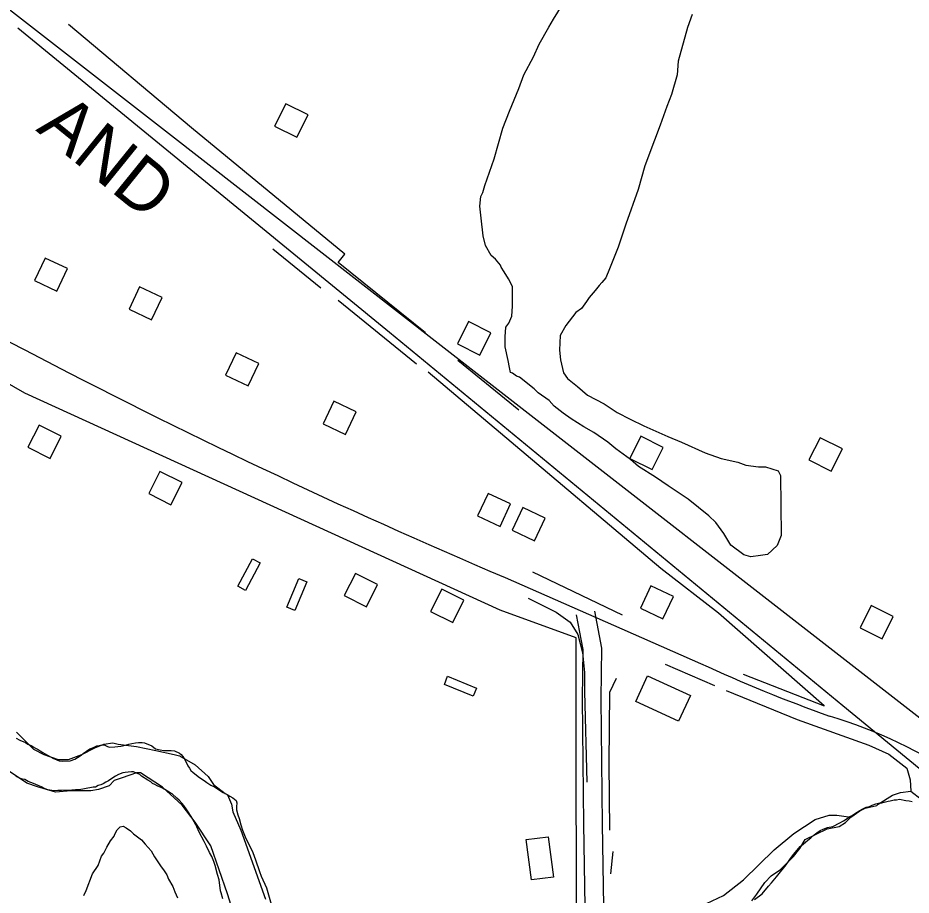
# Model space of a CAD drawing. Extents: x 3250478 to 3288318, y 788638 to 816472.
# Drawn here: x 3257033 to 3258470, y 796061 to 797471 of the extents above; entities that cross this region are included whole.
import ezdxf

# ---------------------------------------------------------------- set-up
doc = ezdxf.new("R2010")
doc.units = 0
for name, color, linetype in [('V-BLDG-OTLN', 7, 'Continuous'), ('V-RAIL-IDEN', 7, 'Continuous'), ('V-RAIL-TRAK', 7, 'Continuous'), ('V-ROAD-CNTR', 7, 'Continuous'), ('V-SITE-VEGE', 7, 'Continuous'), ('V-TOPO-SHOR', 7, 'Continuous')]:
    doc.layers.add(name, color=color, linetype=linetype)

msp = doc.modelspace()

# ---------------------------------------------------------------- linework, layer by layer
at = {"layer": 'V-BLDG-OTLN'}
for points in [[(3257446, 797297.2), (3257481.8, 797279.3), (3257499.7, 797315.1), (3257463.9, 797333)], [(3257059.7, 797048.9), (3257095.9, 797031.8), (3257112.9, 797067.9), (3257076.8, 797085)], [(3257211.8, 797002.7), (3257247.9, 796985.6), (3257265, 797021.7), (3257228.8, 797038.8)], [(3257740.1, 796946.9), (3257775.9, 796929), (3257793.8, 796964.8), (3257758, 796982.7)], [(3257367.1, 796896.6), (3257403.2, 796879.5), (3257420.3, 796915.7), (3257384.2, 796932.8)], [(3257523.9, 796818.5), (3257560, 796801.5), (3257577.1, 796837.6), (3257541, 796854.7)], [(3257102.8, 796798.6), (3257067.1, 796816.5), (3257049.1, 796780.7), (3257084.9, 796762.8)], [(3258017.3, 796762.8), (3258053, 796744.9), (3258070.9, 796780.6), (3258035.2, 796798.5)], [(3258305.4, 796760.5), (3258341.2, 796742.6), (3258359.1, 796778.3), (3258323.3, 796796.2)], [(3257297.1, 796724.1), (3257261.3, 796742), (3257243.4, 796706.3), (3257279.1, 796688.4)], [(3257772.4, 796670.5), (3257808.5, 796653.4), (3257825.6, 796689.6), (3257789.5, 796706.7)], [(3257828, 796647.6), (3257864.2, 796630.5), (3257881.3, 796666.7), (3257845.1, 796683.8)], [(3257422.7, 796594.9), (3257399.2, 796550.7), (3257386.9, 796557.3), (3257410.4, 796601.5)], [(3257497.7, 796564.6), (3257478.6, 796518.4), (3257465.7, 796523.7), (3257484.8, 796569.9)], [(3257611.6, 796560.2), (3257575.8, 796578.1), (3257557.9, 796542.4), (3257593.7, 796524.4)], [(3257750.4, 796534.8), (3257714.7, 796552.8), (3257696.7, 796517), (3257732.5, 796499.1)], [(3258034.2, 796521.9), (3258070.4, 796504.8), (3258087.4, 796541), (3258051.3, 796558.1)], [(3258387.5, 796490.8), (3258423.2, 796472.9), (3258441.1, 796508.6), (3258405.4, 796526.5)], [(3257724.2, 796412.6), (3257770.6, 796393.8), (3257765.3, 796380.8), (3257719, 796399.6)], [(3258095.6, 796340.4), (3258026.7, 796371.9), (3258045.7, 796413.4), (3258114.6, 796381.9)], [(3257859.2, 796085.4), (3257850.8, 796150.2), (3257886, 796154.8), (3257894.5, 796090)]]:
    msp.add_lwpolyline(points, close=True, dxfattribs=at)
at = {"layer": 'V-RAIL-TRAK'}
for p, q in [((3256836.1, 797626.6), (3257270.3, 797289.2)), ((3257270.3, 797289.2), (3257708.9, 796948.1)), ((3257708.9, 796948.1), (3258784.7, 796111.9))]:
    msp.add_line(p, q, dxfattribs=at)
at = {"layer": 'V-ROAD-CNTR'}
for points in [[(3257460.7, 794021.9), (3257497.3, 794112.9), (3257860.4, 794882.3), (3257924.8, 795086.6), (3257932, 795269.1), (3257930.7, 796474.2), (3257808.6, 796519), (3257044, 796867.7), (3256342, 797271.9), (3255916.7, 797438.8), (3254738.6, 797696.6), (3254639.1, 797722.8)], [(3257033, 797455), (3257630.9, 796965.7), (3258360.1, 796365.5), (3258907.8, 795916), (3259260.7, 795624.6)], [(3256332.7, 797305.7), (3256597.4, 797165.1), (3257044.1, 796937.5)], [(3257816.7, 796571.3), (3257991, 796494.9), (3258130.7, 796433.4)], [(3257960.8, 795434.7), (3257959.7, 795538.8), (3257948.6, 795843.8), (3257943.1, 796174.8), (3257941.3, 796376.3), (3257942.4, 796455.5), (3257931.6, 796511.6)], [(3257981.1, 795776.3), (3257978.6, 795844.6), (3257973.1, 796175.2), (3257971.3, 796376.3), (3257972.5, 796458.1), (3257961.1, 796517.3)]]:
    msp.add_lwpolyline(points, dxfattribs=at)
for centre, radius, start, end in [((3261963.5, 806320), 10594, 242.33113, 246.95669), ((3259154.7, 798645.7), 2437.7, 245.163, 250.4344), ((3258105.2, 795581.8), 801.6, 56.0289, 73.0938)]:
    msp.add_arc(centre, radius, start, end, dxfattribs=at)
at = {"layer": 'V-SITE-VEGE'}
for points in [[(3257943.4, 796813.9), (3257922.7, 796826.4), (3257909.9, 796835.7), (3257895.5, 796846.6), (3257887.5, 796856), (3257869.9, 796868.5), (3257863.5, 796874.8), (3257839.6, 796893.5), (3257834.8, 796895), (3257828.4, 796899.7), (3257825.2, 796901.2), (3257823.5, 796909.1), (3257821.8, 796920.2), (3257816.8, 796942.3), (3257816.6, 796958.1), (3257818, 796974), (3257822.7, 796980.4), (3257827.3, 796991.5), (3257828.7, 797007.4), (3257828.4, 797039), (3257821.9, 797051.6), (3257815.4, 797062.6), (3257810.6, 797070.5), (3257809, 797073.6), (3257801, 797083), (3257794.5, 797089.3), (3257784.9, 797105), (3257781.5, 797120.8), (3257778, 797149.3), (3257776.2, 797168.2), (3257777.6, 797184.1), (3257780.7, 797190.5), (3257783.8, 797201.6), (3257799.1, 797244.5), (3257812.8, 797293.8), (3257823.5, 797320.8), (3257839, 797357.4), (3257846.6, 797379.6), (3257862.1, 797408.3), (3257871.4, 797429), (3257886.9, 797456.1), (3257894.7, 797468.9), (3257908.7, 797491.2)], [(3258117.8, 797476.2), (3258110.2, 797455.5), (3258094.9, 797401.5), (3258093.6, 797379.3), (3258084.5, 797347.6), (3258076.8, 797328.5), (3258066.1, 797298.3), (3258056.8, 797274.4), (3258041.5, 797233.1), (3258030.8, 797194.9), (3258010.9, 797139.3), (3257998.6, 797102.7), (3257984.8, 797067.7), (3257978.6, 797053.4), (3257972.4, 797045.4), (3257967.7, 797040.6), (3257961.5, 797032.6), (3257952.1, 797021.4), (3257947.4, 797015.1), (3257939.6, 797003.9), (3257930.2, 796997.4), (3257914.6, 796976.7), (3257905.3, 796960.7), (3257904, 796937), (3257905.7, 796921.2), (3257910.7, 796900.6), (3257917.2, 796891.2), (3257933.1, 796878.7), (3257949.1, 796864.7), (3257976.2, 796850.7), (3257997, 796836.7), (3258017.7, 796825.9), (3258040, 796815), (3258078.2, 796798.1), (3258100.4, 796788.8), (3258138.6, 796771.8), (3258164.1, 796762.6), (3258191.1, 796756.6), (3258203.8, 796752), (3258224.4, 796749.1), (3258235.5, 796749.2), (3258256.1, 796743.1), (3258259.4, 796735.2), (3258260.5, 796638.7), (3258254.4, 796622.8), (3258238.7, 796608.3), (3258227.6, 796606.6), (3258211.8, 796604.9), (3258200.7, 796607.9), (3258179.9, 796623.5), (3258168.6, 796642.4), (3258155.8, 796659.6), (3258144.6, 796670.6), (3258111, 796697.1), (3258079.1, 796718.9), (3258058.3, 796732.9), (3258031.2, 796750), (3258018.4, 796761), (3257994.5, 796778.1), (3257981.7, 796789), (3257959.3, 796804.6), (3257943.4, 796813.9)], [(3257030.1, 796313.2), (3257036.1, 796310), (3257045.3, 796306), (3257049, 796303.8), (3257055.3, 796301), (3257059.4, 796298.4), (3257065.4, 796295.2), (3257069.1, 796292.6), (3257073.2, 796290.1), (3257080.6, 796286.1), (3257090.3, 796280.7), (3257095.8, 796278.2), (3257099.5, 796276.7), (3257105.4, 796276.4), (3257116.9, 796276.6), (3257124.6, 796279.6), (3257133.4, 796284.9), (3257139.9, 796290.1), (3257143.6, 796292.4), (3257148.7, 796295.8), (3257154.6, 796298.4), (3257160.1, 796301.1), (3257163.8, 796301.5), (3257168.2, 796302.3), (3257171.9, 796302.3), (3257176, 796300.1), (3257179.7, 796298.7), (3257188.9, 796299.2), (3257193.7, 796300), (3257198.8, 796300.4), (3257206.2, 796302), (3257211.4, 796303.5), (3257216.1, 796304.7), (3257222.4, 796305.8), (3257226.8, 796306.3), (3257233.1, 796306.3), (3257236.8, 796305.6), (3257248.3, 796300.6), (3257254.6, 796296.2), (3257261.6, 796294.5), (3257267.9, 796293.4), (3257279.4, 796293.6), (3257284.9, 796292.9), (3257293, 796289.3), (3257295.7, 796286.8), (3257300.1, 796281.6), (3257302.4, 796276.5), (3257306.6, 796268.8), (3257309.2, 796265.2), (3257311.4, 796261.1), (3257314.8, 796257.8), (3257325.2, 796249.8), (3257332.7, 796245.1), (3257336.8, 796241.9), (3257343.4, 796237.9), (3257349, 796235), (3257357.2, 796229.6), (3257363.1, 796225.9), (3257370.6, 796222), (3257373.9, 796219.8), (3257378.7, 796217.3), (3257383.9, 796212.9), (3257385.1, 796209.2), (3257384.8, 796202.9), (3257384.8, 796198.1), (3257386.8, 796189.7), (3257389.1, 796184.2), (3257391.8, 796173.9), (3257394.4, 796165.4), (3257399.8, 796151.8), (3257404.3, 796143), (3257410.7, 796129.5), (3257415.3, 796117.7), (3257421.8, 796098.6), (3257424.4, 796091.6), (3257433.1, 796072.5), (3257441.2, 796042.4)], [(3257157.6, 796234.6), (3257154.2, 796234.2), (3257139.9, 796231.5), (3257131.4, 796230.3), (3257125.5, 796230.2), (3257120, 796229.4), (3257103.4, 796229.2), (3257097.1, 796228.8), (3257090.9, 796228.7), (3257081.2, 796230.1), (3257075.7, 796232.2), (3257070.9, 796234.7), (3257065.7, 796236.9), (3257058.3, 796240.5), (3257049.7, 796243.7), (3257044.2, 796246.6), (3257040.5, 796247.3), (3257037.1, 796248.4), (3257030.5, 796251.6)], [(3257362.5, 796054.8), (3257359.8, 796064.7), (3257358.7, 796068), (3257356.6, 796085.7), (3257354.3, 796093.8), (3257350.5, 796108.5), (3257348.2, 796114.7), (3257344.8, 796123.2), (3257341.4, 796129.4), (3257336.5, 796139.7), (3257332.7, 796147), (3257324.8, 796162), (3257320.6, 796170.8), (3257319.1, 796173.8), (3257314.2, 796182.2), (3257311.6, 796187.3), (3257306.7, 796194.7), (3257303.7, 796199.4), (3257299.9, 796204.9), (3257296.6, 796208.6), (3257292.4, 796213.7), (3257288.7, 796217), (3257280.9, 796223.5), (3257276.1, 796226.4), (3257273.5, 796228.2), (3257270.5, 796230), (3257262.3, 796234.4), (3257258.2, 796236.2), (3257253.1, 796238.7), (3257249.7, 796240.5), (3257246.7, 796243), (3257241.9, 796245.6), (3257231.9, 796252.1), (3257228.9, 796254.6), (3257223.7, 796256.8), (3257219.2, 796258.9), (3257215.6, 796259.3), (3257210.4, 796258.8), (3257205.6, 796258.1), (3257201.6, 796257.6), (3257194.6, 796255), (3257190.2, 796252.3), (3257184, 796248.2), (3257178.8, 796244.5), (3257174.4, 796242.2), (3257170.4, 796239.9), (3257166.4, 796238), (3257162, 796236.9), (3257157.6, 796234.6)], [(3258268.6, 796109.5), (3258272.3, 796114.7), (3258275.9, 796119.5), (3258281, 796126.6), (3258291.2, 796138.9), (3258296.3, 796143), (3258303.6, 796149.4), (3258308.4, 796153.1), (3258313.8, 796158), (3258318.2, 796161), (3258323.3, 796164.7), (3258328.1, 796167), (3258335.1, 796169.7), (3258343.9, 796171.2), (3258354.9, 796177.3), (3258361.2, 796180.3), (3258365.2, 796182.9), (3258371, 796187.4), (3258375.1, 796188.9), (3258378.4, 796191.5), (3258387.2, 796196.8), (3258391.9, 796199.5), (3258397.4, 796202.1), (3258402.6, 796203.6), (3258407.3, 796205.5), (3258412.9, 796207.4), (3258417.3, 796208.6), (3258422.8, 796209.4), (3258426.5, 796210.2), (3258432.7, 796212.1), (3258436, 796212.5), (3258442.3, 796214.1), (3258446.4, 796214.1), (3258451.1, 796214.9), (3258461.1, 796213.2), (3258466.7, 796212.5), (3258471.5, 796211.4)], [(3257139, 796060.5), (3257142.8, 796068.4), (3257153.2, 796094.9), (3257161.9, 796108.7), (3257167.6, 796123.4), (3257171.4, 796128.3), (3257176.2, 796138.1), (3257181.9, 796148), (3257187.7, 796155.9), (3257188.7, 796158.8), (3257192.5, 796165.7), (3257197.3, 796170.6), (3257202.2, 796171.7), (3257207.1, 796168.8), (3257214, 796164), (3257219, 796159.2), (3257231.8, 796149.5), (3257237.7, 796142.8), (3257247.6, 796132.1), (3257252.6, 796122.4), (3257262.6, 796107.9), (3257268.5, 796100.1), (3257272.5, 796093.3), (3257275.5, 796086.5), (3257282.5, 796074.9), (3257285.5, 796066.1), (3257289.5, 796056.4)], [(3258218, 796053.6), (3258230.1, 796062.9), (3258240.3, 796075.2), (3258245.4, 796080.8), (3258253, 796090.5), (3258257.7, 796095.7), (3258264.6, 796104.3), (3258268.6, 796109.5)]]:
    msp.add_lwpolyline(points, dxfattribs=at)
at = {"layer": 'V-TOPO-SHOR'}
for p, q in [((3257520.3, 797036.7), (3257443.3, 797099.1)), ((3257674.2, 796914.6), (3257548.1, 797016.8)), ((3257838.7, 796840.5), (3257740.5, 796920.2)), ((3257860.5, 796580.8), (3258005.2, 796511.7)), ((3258074.1, 796432.1), (3258153.7, 796397.6)), ((3257986.5, 796095), (3257990.4, 796130.9))]:
    msp.add_line(p, q, dxfattribs=at)
for points in [[(3257688.8, 796965), (3257548.2, 797077.8), (3257558.8, 797091.1), (3257312, 797294.2), (3257114.3, 797460.1)], [(3258199.5, 796415.8), (3258329.6, 796365.3), (3258159.7, 796514), (3258066.9, 796585.7), (3257809.5, 796803.4), (3257692.8, 796901.6)], [(3257853.9, 796538.3), (3257899, 796515.7), (3257921.5, 796499.8), (3257933.5, 796479.9), (3257941.4, 796450.7), (3257944.1, 796418.9), (3257944.1, 796388.3), (3257948, 796242.4)], [(3257985.1, 796165.4), (3257983.8, 796272.9), (3257985.2, 796387), (3257995.8, 796409.5)], [(3258172.3, 796389.6), (3258286.4, 796343.1), (3258401.9, 796301.9), (3258433.7, 796287.3), (3258462.9, 796264.8), (3258468.2, 796246.2), (3258469.1, 796228)], [(3257030.8, 796322.8), (3257043.4, 796310.2), (3257058, 796295.5), (3257074.8, 796287.1), (3257097.9, 796278.7), (3257114.6, 796278.7), (3257135.6, 796287.1), (3257156.6, 796297.6), (3257171.3, 796303.8), (3257185.9, 796305.9), (3257194.3, 796303.8), (3257223.7, 796299.6), (3257255.1, 796293.3), (3257284.5, 796287), (3257292.9, 796284.9), (3257318, 796270.2), (3257339, 796251.4), (3257347.4, 796238.8), (3257366.2, 796224.1), (3257370.4, 796222), (3257376.7, 796207.3), (3257378.8, 796194.7), (3257391.4, 796165.4), (3257431.2, 796054.3)], [(3257410.2, 795934.7), (3257370.4, 796062.7), (3257343.1, 796140.2), (3257318, 796178), (3257297, 796205.3), (3257265.6, 796234.6), (3257230, 796257.7), (3257223.7, 796257.7), (3257200.6, 796249.3), (3257188, 796245.1), (3257179.6, 796236.7), (3257162.9, 796230.5), (3257150.3, 796228.4), (3257118.8, 796228.4), (3257093.7, 796226.3), (3257064.3, 796234.7), (3257047.5, 796241), (3257016.1, 796262)], [(3258213.3, 796051.9), (3258221.7, 796062.4), (3258234.2, 796081.3), (3258244.7, 796091.8), (3258259.4, 796102.2), (3258280.4, 796123.2), (3258290.9, 796135.8), (3258299.3, 796150.4), (3258334.9, 796167.2), (3258353.8, 796171.4), (3258364.3, 796177.7), (3258372.7, 796186.1), (3258387.3, 796196.6), (3258395.7, 796200.7), (3258414.6, 796204.9), (3258416.7, 796207), (3258439.8, 796221.7), (3258452.4, 796225.9), (3258469.1, 796228), (3258485.9, 796215.4)], [(3258031.6, 796043.3), (3258104.5, 796044.6), (3258140.4, 796047.2), (3258168.2, 796060.5), (3258200.1, 796085.7), (3258249.2, 796133.5), (3258281.1, 796160), (3258315.6, 796182.5), (3258338.1, 796189.2), (3258350.1, 796189.2), (3258372.7, 796186.1)]]:
    msp.add_lwpolyline(points, dxfattribs=at)

# ---------------------------------------------------------------- texts
at = {"layer": 'V-RAIL-IDEN'}
msp.add_text('AND', height=83, rotation=320.9744, dxfattribs=at).set_placement((3257060.6, 797290.4))

doc.saveas('drawing.dxf')
